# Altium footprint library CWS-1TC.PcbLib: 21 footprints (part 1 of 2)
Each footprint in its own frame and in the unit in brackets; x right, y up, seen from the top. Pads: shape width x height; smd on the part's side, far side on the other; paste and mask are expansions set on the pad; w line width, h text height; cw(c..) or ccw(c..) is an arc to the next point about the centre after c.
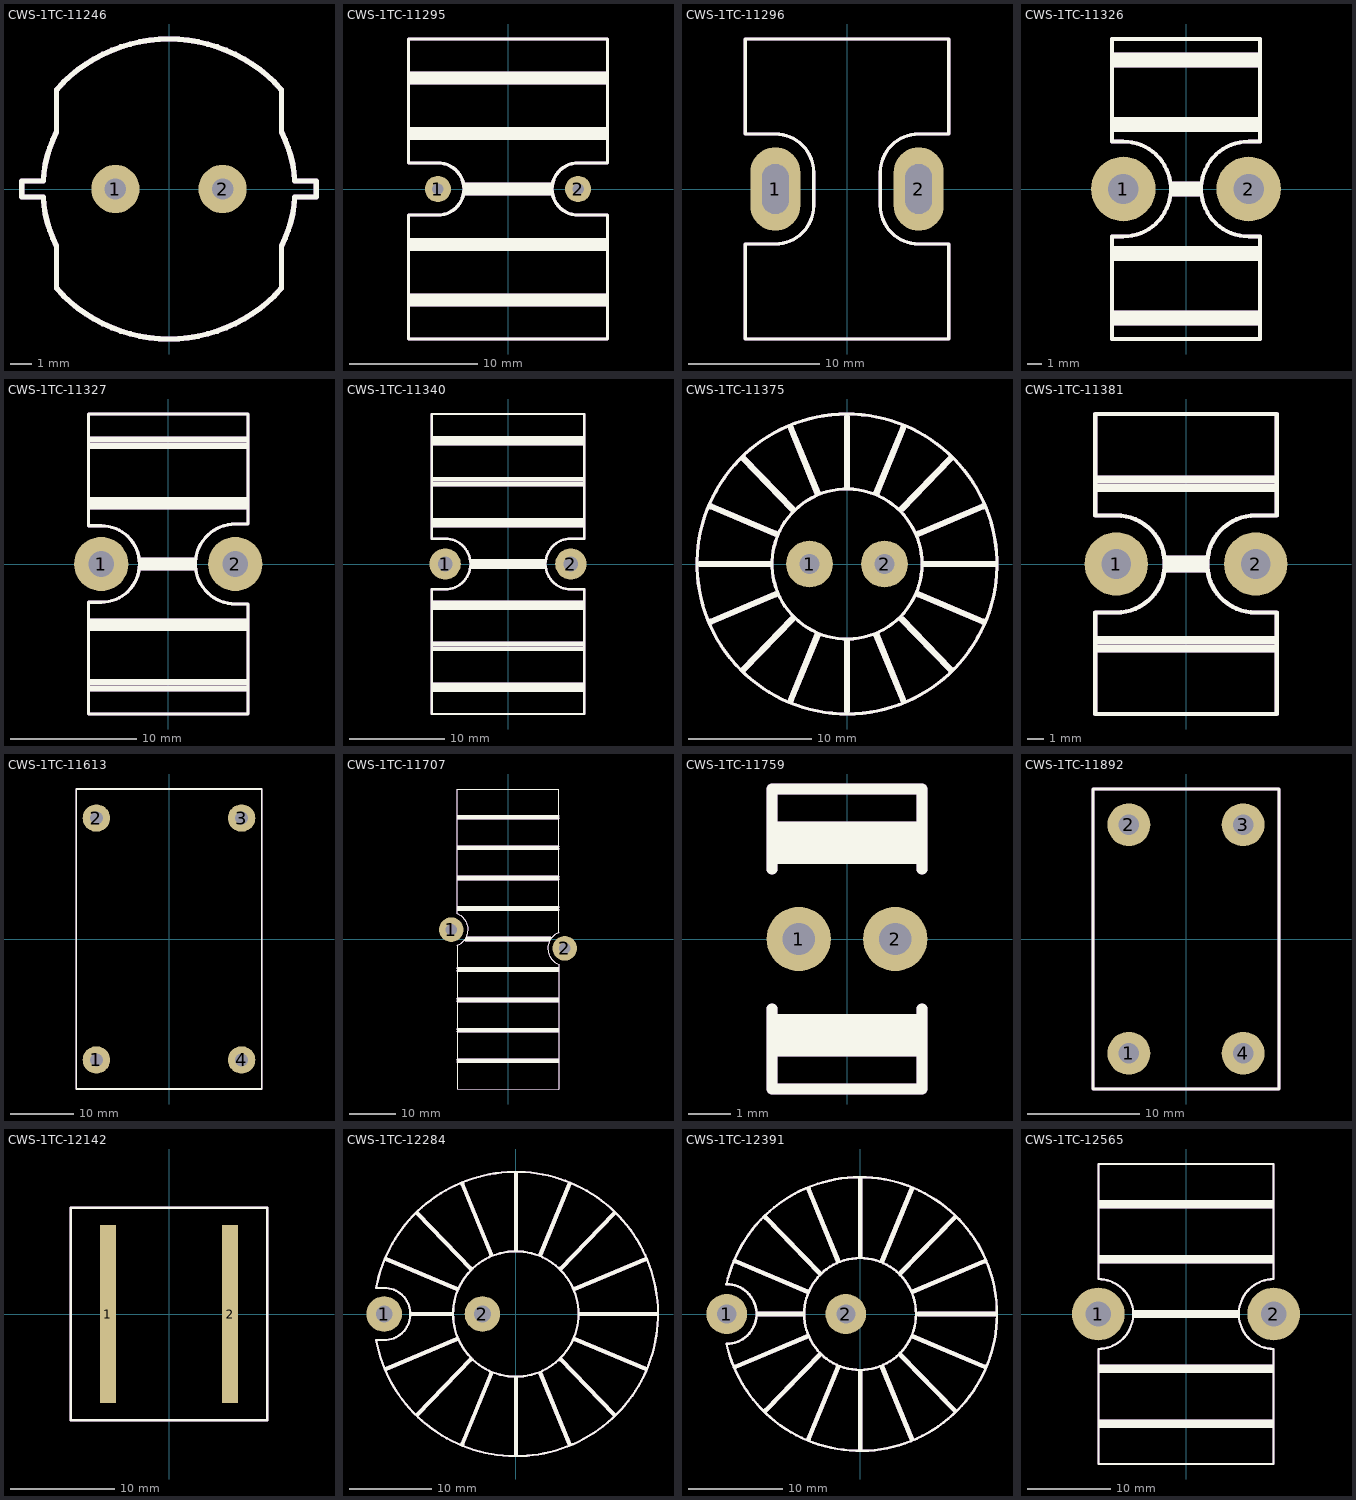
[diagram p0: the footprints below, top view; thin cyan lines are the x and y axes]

## CWS-1TC-11246 [mil]
pads (2):
  round 90 hole 40: 1(-100,0) 2(100,0)
Top Overlay:
  lines w10: -210.1,185.09 cw(c0,0) 210.1,185.09 ; -210,-185 -210,-106.54 cw(c0,0) -235,-15 -275,-15 -275,15 -235,15 cw(c0,0) -210,106.54 -210,185 ; 210,-185 210,-106.54 ccw(c0,0) 235,-15 275,-15 275,15 235,15 ccw(c0,0) 210,106.54 210,185 ; -210.1,-185.09 ccw(c0,0) 210.1,-185.09 cw(c0,0) -210.1,-185.09
Mechanical 29:
  lines w10: -210.1,185.09 cw(c0,0) 210.1,185.09 ; -210,-185 -210,-106.54 cw(c0,0) -235,-15 -275,-15 -275,15 -235,15 cw(c0,0) -210,106.54 -210,185 ; 210,-185 210,-106.54 ccw(c0,0) 235,-15 275,-15 275,15 235,15 ccw(c0,0) 210,106.54 210,185 ; -210.1,-185.09 ccw(c0,0) 210.1,-185.09 cw(c0,0) -210.1,-185.09
  text "'.Designator'" at -1750,-64.85 h400

## CWS-1TC-11295 [mil]
pads (2):
  round 80 hole 35: 1(-215,0) 2(215,0)
Top Overlay:
  lines w10: -305,-460 305,-460 305,-80 215,-80 cw(c215,0) 215,80 305,80 305,460 -305,460 -305,80 -215,80 cw(c-215,0) -215,-80 -305,-80 -305,-460
  lines w19.68: -300,-350 300,-350 ; -300,-330 300,-330 ; -300,-180 300,-180 ; -300,-160 300,-160 ; -300,160 300,160 ; -300,180 300,180 ; -300,330 300,330 ; -300,350 300,350 ; -130,-10 130,-10 ; -130,10 130,10
Mechanical 29:
  lines w10: -305,-460 305,-460 305,-80 215,-80 cw(c215,0) 215,80 305,80 305,460 -305,460 -305,80 -215,80 cw(c-215,0) -215,-80 -305,-80 -305,-460
  lines w19.68: -300,-350 300,-350 ; -300,-330 300,-330 ; -300,-180 300,-180 ; -300,-160 300,-160 ; -300,160 300,160 ; -300,180 300,180 ; -300,330 300,330 ; -300,350 300,350 ; -130,-10 130,-10 ; -130,10 130,10
  text "'.Designator'" at -1750,-64.85 h400

## CWS-1TC-11296 [mil]
pads (2):
  oval 150x250 hole 80 slot 150 at 90 deg: 1(-215,0) 2(215,0)
Top Overlay:
  lines w10: -305,-450 305,-450 305,-165 215,-165 cw(c215,-50) 100,-50 100,50 cw(c215,50) 215,165 305,165 305,450 -305,450 -305,165 -215,165 cw(c-215,50) -100,50 -100,-50 cw(c-215,-50) -215,-165 -305,-165 -305,-450
Mechanical 29:
  lines w10: -305,-450 305,-450 305,-165 215,-165 cw(c215,-50) 100,-50 100,50 cw(c215,50) 215,165 305,165 305,450 -305,450 -305,165 -215,165 cw(c-215,50) -100,50 -100,-50 cw(c-215,-50) -215,-165 -305,-165 -305,-450
  text "'.Designator'" at -1750,-64.85 h400

## CWS-1TC-11326 [mil]
pads (2):
  round 170 hole 80: 1(-165,0) 2(165,0)
Top Overlay:
  lines w10: -195,-395 195,-395 195,-125 165,-125 cw(c165,0) 165,125 195,125 195,395 -195,395 -195,125 -165,125 cw(c-165,0) -165,-125 -195,-125 -195,-395
  lines w19.68: -190,-350 190,-350 ; -190,-330 190,-330 ; -190,-180 190,-180 ; -190,-160 190,-160 ; -190,160 190,160 ; -190,180 190,180 ; -190,330 190,330 ; -190,350 190,350 ; -35,-10 35,-10 ; -35,10 35,10
Mechanical 29:
  lines w10: -195,-395 195,-395 195,-125 165,-125 cw(c165,0) 165,125 195,125 195,395 -195,395 -195,125 -165,125 cw(c-165,0) -165,-125 -195,-125 -195,-395
  lines w19.68: -190,-350 190,-350 ; -190,-330 190,-330 ; -190,-180 190,-180 ; -190,-160 190,-160 ; -190,160 190,160 ; -190,180 190,180 ; -190,330 190,330 ; -190,350 190,350 ; -35,-10 35,-10 ; -35,10 35,10
  text "'.Designator'" at -1750,-64.85 h400

## CWS-1TC-11327 [mil]
pads (2):
  round 170 hole 80: 1(-210,0) 2(210,0)
Top Overlay:
  lines w10: -250,-470 -250,-120 -210,-120 ccw(c-210,0) -210,120 -250,120 -250,470 250,470 250,125 210,125 ccw(c210,0) 210,-125 250,-125 250,-470 -250,-470
  lines w19.68: -245,-390 245,-390 ; -245,-370 245,-370 ; -245,-200 245,-200 ; -245,-180 245,-180 ; -245,180 245,180 ; -245,200 245,200 ; -245,370 245,370 ; -245,390 245,390 ; -85,-10 80,-10 ; -85,10 80,10
Mechanical 29:
  lines w10: -250,-470 -250,-120 -210,-120 ccw(c-210,0) -210,120 -250,120 -250,470 250,470 250,125 210,125 ccw(c210,0) 210,-125 250,-125 250,-470 -250,-470
  lines w19.68: -245,-390 245,-390 ; -245,-370 245,-370 ; -245,-200 245,-200 ; -245,-180 245,-180 ; -245,180 245,180 ; -245,200 245,200 ; -245,370 245,370 ; -245,390 245,390 ; -85,-10 80,-10 ; -85,10 80,10
  text "'.Designator'" at -1750,-64.85 h400

## CWS-1TC-11340 [mil]
pads (2):
  round 130 hole 60: 1(-260,0) 2(260,0)
Top Overlay:
  lines w10: -315,-620 -315,-105 -260,-105 ccw(c-260,0) -260,105 -315,105 -315,620 315,620 315,105 260,105 ccw(c260,0) 260,-105 315,-105 315,-620 -315,-620
  lines w19.68: -310,-520 310,-520 ; -310,-500 310,-500 ; -310,-350 310,-350 ; -310,-330 310,-330 ; -310,-180 310,-180 ; -310,-160 310,-160 ; -310,160 310,160 ; -310,180 310,180 ; -310,330 310,330 ; -310,350 310,350 ; -310,500 310,500 ; -310,520 310,520 ; -150,-10 150,-10 ; -150,10 150,10
Mechanical 29:
  lines w10: -315,-620 -315,-105 -260,-105 ccw(c-260,0) -260,105 -315,105 -315,620 315,620 315,105 260,105 ccw(c260,0) 260,-105 315,-105 315,-620 -315,-620
  lines w19.68: -310,-520 310,-520 ; -310,-500 310,-500 ; -310,-350 310,-350 ; -310,-330 310,-330 ; -310,-180 310,-180 ; -310,-160 310,-160 ; -310,160 310,160 ; -310,180 310,180 ; -310,330 310,330 ; -310,350 310,350 ; -310,500 310,500 ; -310,520 310,520 ; -150,-10 150,-10 ; -150,10 150,10
  text "'.Designator'" at -1750,-64.85 h400

## CWS-1TC-11375 [mil]
pads (2):
  round 150 hole 65: 1(-120,0) 2(120,0)
Top Overlay:
  circle w10: c0,0 r240
  lines w10: -472.43,-84.92 ccw(c0,0) 472.45,84.8 ccw(c0,0) -472.43,-84.92
  lines w19.68: -470,0 -245,0 ; -436.29,-184.87 -229.12,-97.08 ; -436.29,184.87 -229.12,97.08 ; -331.02,-337.27 -174.41,-175.73 ; -331.02,337.27 -174.41,175.73 ; -179.64,-435.52 -94.32,-227.33 ; -179.64,435.52 -94.32,227.33 ; 0,-470 0,-245 ; 0,245 0,470 ; 94.32,-227.33 179.64,-435.52 ; 94.32,227.33 179.64,435.52 ; 174.41,-175.73 331.02,-337.27 ; 174.41,175.73 331.02,337.27 ; 229.12,-97.08 436.29,-184.87 ; 229.12,97.08 436.29,184.87 ; 245,0 475,0
Mechanical 29:
  circle w10: c0,0 r240
  lines w10: -472.43,-84.92 ccw(c0,0) 472.45,84.8 ccw(c0,0) -472.43,-84.92
  lines w19.68: -470,0 -245,0 ; -436.29,-184.87 -229.12,-97.08 ; -436.29,184.87 -229.12,97.08 ; -331.02,-337.27 -174.41,-175.73 ; -331.02,337.27 -174.41,175.73 ; -179.64,-435.52 -94.32,-227.33 ; -179.64,435.52 -94.32,227.33 ; 0,-470 0,-245 ; 0,245 0,470 ; 94.32,-227.33 179.64,-435.52 ; 94.32,227.33 179.64,435.52 ; 174.41,-175.73 331.02,-337.27 ; 174.41,175.73 331.02,337.27 ; 229.12,-97.08 436.29,-184.87 ; 229.12,97.08 436.29,184.87 ; 245,0 475,0
  text "'.Designator'" at -290,145.15 h400

## CWS-1TC-11381 [mil]
pads (2):
  round 150 hole 70: 1(-165,0) 2(165,0)
Top Overlay:
  lines w10: -215,-355 -215,-115 -165,-115 ccw(c-165,0) -165,115 -215,115 -215,355 215,355 215,115 165,115 ccw(c165,0) 165,-115 215,-115 215,-355 -215,-355
  lines w19.68: -210,-200 210,-200 ; -210,-180 210,-180 ; -210,180 210,180 ; -210,200 210,200 ; -45,-10 45,-10 ; -45,10 45,10
Mechanical 29:
  lines w10: -215,-355 -215,-115 -165,-115 ccw(c-165,0) -165,115 -215,115 -215,355 215,355 215,115 165,115 ccw(c165,0) 165,-115 215,-115 215,-355 -215,-355
  lines w19.68: -210,-200 210,-200 ; -210,-180 210,-180 ; -210,180 210,180 ; -210,200 210,200 ; -45,-10 45,-10 ; -45,10 45,10
  text "'.Designator'" at -1750,-64.85 h400

## CWS-1TC-11613 [mil]
pads (4):
  round 170 hole 80: 1(-450,-750) 2(-450,750) 3(450,750) 4(450,-750)
Top Overlay:
  lines w10: -575,-930 -575,110 -575,930 575,930 575,110 575,-930 -575,-930
Mechanical 29:
  lines w10: -575,-930 -575,110 -575,930 575,930 575,110 575,-930 -575,-930
  text "'.Designator'" at -1750,-64.85 h400

## CWS-1TC-11707 [mil]
pads (2):
  round 210 hole 100: 1(-485,80) 2(485,-80)
Top Overlay:
  lines w10: -435,-56.09 -435,-1280 435,-1280 435,-216.09 ; -435,215.97 -435,1280 435,1280 435,55.97 ; -434.96,-56.09 ccw(c-485,80) -434.64,215.97 ; 434.64,55.97 ccw(c485,-80) 434.96,-216.09
  lines w19.68: -430,-1050 430,-1050 ; -430,-1030 430,-1030 ; -430,-790 430,-790 ; -430,-770 430,-770 ; -430,-530 430,-530 ; -430,-510 430,-510 ; -430,-270 430,-270 ; -430,-250 430,-250 ; -430,250 430,250 ; -430,270 430,270 ; -430,510 430,510 ; -430,530 430,530 ; -430,770 430,770 ; -430,790 430,790 ; -430,1030 430,1030 ; -430,1050 430,1050 ; -363,-10 352,-10 ; -352,10 362,10
Mechanical 29:
  lines w10: -435,-56.09 -435,-1280 435,-1280 435,-216.09 ; -435,215.97 -435,1280 435,1280 435,55.97 ; -434.96,-56.09 ccw(c-485,80) -434.64,215.97 ; 434.64,55.97 ccw(c485,-80) 434.96,-216.09
  lines w19.68: -430,-1050 430,-1050 ; -430,-1030 430,-1030 ; -430,-790 430,-790 ; -430,-770 430,-770 ; -430,-530 430,-530 ; -430,-510 430,-510 ; -430,-270 430,-270 ; -430,-250 430,-250 ; -430,250 430,250 ; -430,270 430,270 ; -430,510 430,510 ; -430,530 430,530 ; -430,770 430,770 ; -430,790 430,790 ; -430,1030 430,1030 ; -430,1050 430,1050 ; -363,-10 352,-10 ; -352,10 362,10
  text "'.Designator'" at -1750,-64.85 h400

## CWS-1TC-11759 [mil]
pads (2):
  round 60 hole 30: 1(-45,0) 2(45,0)
Top Overlay:
  lines w10: -70,-65 -70,-140 70,-140 70,-65 ; -70,65 -70,140 70,140 70,65
  lines w19.68: -65,-100 65,-100 ; -65,-80 65,-80 ; -65,80 65,80 ; -65,100 65,100
Mechanical 29:
  lines w10: -70,-65 -70,-140 70,-140 70,-65 ; -70,65 -70,140 70,140 70,65
  lines w19.68: -65,-100 65,-100 ; -65,-80 65,-80 ; -65,80 65,80 ; -65,100 65,100
  text "'.Designator'" at -1750,-64.85 h400

## CWS-1TC-11892 [mil]
pads (4):
  round 150 hole 71: 1(-200,-400) 2(-200,400) 3(200,400) 4(200,-400)
Top Overlay:
  lines w10: -325,-525 -325,110 -325,525 325,525 325,110 325,-525 -325,-525
Mechanical 29:
  lines w10: -325,-525 -325,110 -325,525 325,525 325,110 325,-525 -325,-525
  text "'.Designator'" at -1750,-64.85 h400

## CWS-1TC-12142 [mil]
pads (2):
  rect 60x670 smd: 1(-230,0) 2(230,0)
Top Overlay:
  lines w10: -370,-400 37.5,-400 370,-400 370,400 37.5,400 -370,400 -370,-400
Mechanical 29:
  lines w10: -370,-400 37.5,-400 370,-400 370,400 37.5,400 -370,400 -370,-400
  text "'.Designator'" at -1750,-64.85 h400

## CWS-1TC-12284 [mil]
pads (2):
  round 170 hole 80: 1(-630,0) 2(-160,0)
Top Overlay:
  circle w10: c0,0 r300
  lines w10: -668.3,-125.62 ccw(c0,0) 669.3,120.14 ccw(c0,0) -668.41,125 -630,125 cw(c-630,0) -630,-125 -668.3,-125
  lines w19.68: -621.87,-263.5 -280.49,-118.85 ; -621.87,263.5 -280.49,118.85 ; -500,0 -305,0 ; -470.09,-480.72 -213.7,-216.26 ; -470.09,480.72 -213.7,216.26 ; -256.38,-622.77 -117.96,-285.03 ; -256.38,622.77 -117.96,285.03 ; 0,-670 0,-305 ; 0,305 0,670 ; 117.96,-285.03 256.38,-622.77 ; 117.96,285.03 256.38,622.77 ; 213.7,-216.26 470.09,-480.72 ; 213.7,216.26 470.09,480.72 ; 280.49,-118.85 621.87,-263.5 ; 280.49,118.85 621.87,263.5 ; 305,0 670,0
Mechanical 29:
  circle w10: c0,0 r300
  lines w10: -668.3,-125.62 ccw(c0,0) 669.3,120.14 ccw(c0,0) -668.41,125 -630,125 cw(c-630,0) -630,-125 -668.3,-125
  lines w19.68: -621.87,-263.5 -280.49,-118.85 ; -621.87,263.5 -280.49,118.85 ; -500,0 -305,0 ; -470.09,-480.72 -213.7,-216.26 ; -470.09,480.72 -213.7,216.26 ; -256.38,-622.77 -117.96,-285.03 ; -256.38,622.77 -117.96,285.03 ; 0,-670 0,-305 ; 0,305 0,670 ; 117.96,-285.03 256.38,-622.77 ; 117.96,285.03 256.38,622.77 ; 213.7,-216.26 470.09,-480.72 ; 213.7,216.26 470.09,480.72 ; 280.49,-118.85 621.87,-263.5 ; 280.49,118.85 621.87,263.5 ; 305,0 670,0
  text "'.Designator'" at -290,145.15 h400

## CWS-1TC-12391 [mil]
pads (2):
  round 170 hole 80: 1(-560,0) 2(-60,0)
Top Overlay:
  circle w10: c0,0 r235
  lines w10: -561.37,124.99 cw(c-560,0) -561.19,-124.99 ; -561.25,124.99 cw(c0,0) 565.95,101.59 cw(c0,0) -561.19,-125.27
  lines w19.68: -525.19,-222.54 -224.88,-95.29 ; -525.19,222.54 -220.64,93.49 ; -430,0 -240,0 ; -397,-405.33 -169.41,-170.57 ; -397,405.33 -169.41,170.57 ; -216.56,-525.61 -92.88,-223.82 ; -216.56,525.61 -93.6,225.58 ; 0,-569 0,-240 ; 0,240 0,569 ; 92.88,-223.82 216.56,-525.61 ; 92.88,223.82 216.56,525.61 ; 169.41,-170.57 397,-405.33 ; 169.41,170.57 397,405.33 ; 220.64,-93.49 525.19,-222.54 ; 220.64,93.49 525.19,222.54 ; 245,0 570,0
Mechanical 29:
  circle w10: c0,0 r235
  lines w10: -561.37,124.99 cw(c-560,0) -561.19,-124.99 ; -561.25,124.99 cw(c0,0) 565.95,101.59 cw(c0,0) -561.19,-125.27
  lines w19.68: -525.19,-222.54 -224.88,-95.29 ; -525.19,222.54 -220.64,93.49 ; -430,0 -240,0 ; -397,-405.33 -169.41,-170.57 ; -397,405.33 -169.41,170.57 ; -216.56,-525.61 -92.88,-223.82 ; -216.56,525.61 -93.6,225.58 ; 0,-569 0,-240 ; 0,240 0,569 ; 92.88,-223.82 216.56,-525.61 ; 92.88,223.82 216.56,525.61 ; 169.41,-170.57 397,-405.33 ; 169.41,170.57 397,405.33 ; 220.64,-93.49 525.19,-222.54 ; 220.64,93.49 525.19,222.54 ; 245,0 570,0
  text "'.Designator'" at -290,145.15 h400

## CWS-1TC-12565 [mil]
pads (2):
  round 250 hole 120: 1(-415,0) 2(415,0)
Top Overlay:
  lines w10: 415,-710 -415,-710 -415,-165 ccw(c-415,0) -415,165 -415,710 415,710 ; 415,-709.9 415,-165 cw(c415,0) 415,165 415,709.9
  lines w19.68: -410,-530 410,-530 ; -410,-510 410,-510 ; -410,-270 410,-270 ; -410,-250 410,-250 ; -410,250 410,250 ; -410,270 410,270 ; -410,510 410,510 ; -410,530 410,530 ; -245,-10 244,-10 ; -245,10 244,10
Mechanical 29:
  lines w10: 415,-710 -415,-710 -415,-165 ccw(c-415,0) -415,165 -415,710 415,710 ; 415,-709.9 415,-165 cw(c415,0) 415,165 415,709.9
  lines w19.68: -410,-530 410,-530 ; -410,-510 410,-510 ; -410,-270 410,-270 ; -410,-250 410,-250 ; -410,250 410,250 ; -410,270 410,270 ; -410,510 410,510 ; -410,530 410,530 ; -245,-10 244,-10 ; -245,10 244,10
  text "'.Designator'" at -1750,-64.85 h400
